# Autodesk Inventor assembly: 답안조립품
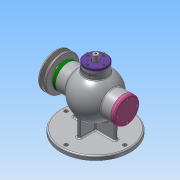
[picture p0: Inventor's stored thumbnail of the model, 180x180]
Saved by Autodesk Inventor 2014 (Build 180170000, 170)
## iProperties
Created: 2020-08
Part Number: 답안조립품
Document SubType Name: Assembly
Designer: net
Author: net
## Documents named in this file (18)
- C:\Users\net\Desktop\700806V1045\답안조립품.iam
- C:\Users\net\Desktop\700806V1045\본체.ipt
- C:\Users\net\Desktop\700806V1045\멈춤링 15x1.ipt
- C:\Users\net\Desktop\700806V1045\멈춤링 35x1.6.ipt
- 멈춤링 35x1.6.ipt
- C:\Users\net\Desktop\700806V1045\베어링 6202.ipt
- 베어링 6202.ipt
- C:\Users\net\Desktop\700806V1045\칼라.ipt
- C:\Users\net\Desktop\700806V1045\편심축.ipt
- C:\Users\net\Desktop\700806V1045\앞커버.ipt
- C:\Users\net\Desktop\700806V1045\오일 실 15 30 7.ipt
- C:\Users\net\Desktop\700806V1045\슬라이드.ipt
- C:\Users\net\Desktop\700806V1045\상부커버.ipt
- C:\Users\net\Desktop\700806V1045\키 3x3x12.ipt
- C:\Users\net\Desktop\700806V1045\V-벨트풀리.ipt
- C:\Users\net\Desktop\700806V1045\너트 M8.ipt
- C:\Users\net\Desktop\700806V1045\뒤커버.ipt
- C:\Users\net\Desktop\700806V1045\볼트 M4.ipt
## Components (1 placed, 1 different names)
1. V-벨트풀리:1
